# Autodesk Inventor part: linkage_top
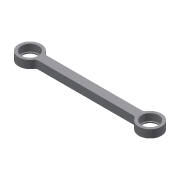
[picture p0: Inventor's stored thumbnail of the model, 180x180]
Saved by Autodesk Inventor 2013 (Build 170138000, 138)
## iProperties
Created: 2013-11
Part Number: linkage_top
Material: Generic
Document SubType Name: Modeling
Designer: Jonas
Density: 1 g/cm^3
Author: Jonas
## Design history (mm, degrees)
sketch "Sketch7"
  geometry: L1 (0, -2.5)-(0, 2.5); L2 (0, 2.5)-(-28.892, 2.5); L3 (-28.892, -2.5)-(0, -2.5); A1 r 6.6 centre (-35, 0) between (-28.892, 2.5) and (-28.892, -2.5); 2 further points
  constraints: 6 end point, 2 coincident, 2 point on circle, 1 centre point, 1 horizontal alignment, 1 midpoint, 1 parallel, 1 perpendicular, 1 vertical
  dimensions: "d15" = 5 distance between parallel lines of L3 L2; "d17" = 13.2 diameter of A1; "d18" = 35 distance of point (0, 0) A1.centre
extrude "Extrusion4" new body sketch "Sketch7" distance "d19" = 4.6; taper "d20" = 0 deg
sketch "Sketch8"
  geometry: C1 r 5 at (-35, 0); A1 r 6.6 centre (-35, 0) between (-28.892, 2.5) and (-28.892, -2.5) reference; 1 further point
  constraints: 1 centre point, 1 coincident
  dimensions: "d21" = 10 diameter of C1
extrude "Extrusion5" cut sketch "Sketch8" distance "d22" = 4; taper "d23" = 0 deg
sketch "Sketch9"
  geometry: C1 r 5 at (0, 0) reference; C2 r 4.45 at (0, 0); 1 further point
  constraints: 1 centre point, 1 coincident
  dimensions: "d25" = 8.9 diameter of C2
extrude "Extrusion6" cut sketch "Sketch9" stored distance "d27" = 4; taper "d28" = 0 deg
fillet "Fillet1" dims "d24" = 2
mirror "Mirror1"
body "Solid3"
